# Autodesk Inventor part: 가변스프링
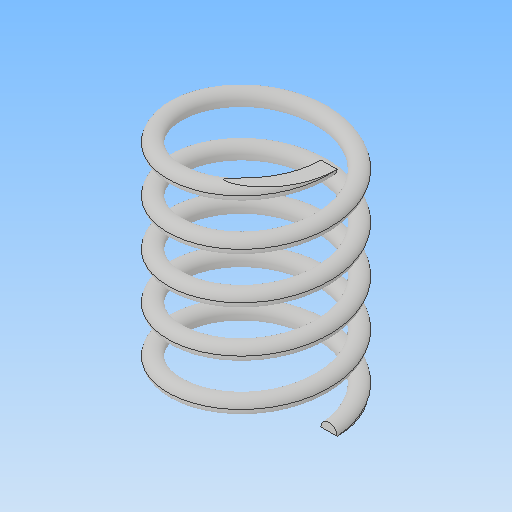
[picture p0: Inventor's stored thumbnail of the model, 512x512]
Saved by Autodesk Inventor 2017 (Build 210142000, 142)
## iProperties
Part Number: 가변스프링
Material: 일반
Document SubType Name: Modeling
Designer: MRC
Density: 1 g/cm^3
Appearance: 기본값
Author: MRC
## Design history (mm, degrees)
sketch "스케치1"
  geometry: L1 (0, 0)-(9, 0); L2 (9, 0)-(9, 28.5); L3 (9, 28.5)-(0, 28.5); L4 (0, 28.5)-(0, 0); C1 r 1 at (9, 0)
  constraints: 8 end point, 2 parallel, 1 centre point, 1 coincident, 1 horizontal, 1 perpendicular
  dimensions: "d0" = 18 diameter of L2 L4; "d1" = 2 diameter of C1; "d2" = 28.5 distance of L3.end L1.start (derived)
feature "코일1" sketch "스케치1" pitch "d3" = 10; turns "d5" = 5; dims "d4" = 28.5 (= d2), "d6" = 0, angle "d7" = 90 deg, angle "d8" = 90 deg, "d9" = 0, "d10" = 0
sketch "스케치2"
  geometry: L1 (28.5, 19.913)-(0, 19.913); L2 (0, 19.913)-(0, -19.913); L3 (0, -19.913)-(28.5, -19.913); L4 (28.5, -19.913)-(28.5, 19.913); 2 further points
  constraints: 8 end point, 2 parallel, 1 coincident, 1 horizontal, 1 midpoint, 1 perpendicular
  dimensions: "d11" = 28.5 distance between parallel lines of L2 L4 (= d2); "d12" = 39.82623 distance of L3.end L1.start
extrude "돌출1" sketch "스케치2" stored distance "d13" = 67.75; taper "d14" = 0 deg
node "솔리드1"
